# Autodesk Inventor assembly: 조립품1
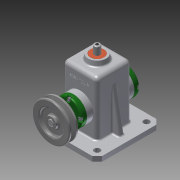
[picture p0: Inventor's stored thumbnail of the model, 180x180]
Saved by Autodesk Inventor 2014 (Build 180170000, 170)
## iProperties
Created: 2016-02
Part Number: 조립품1
Document SubType Name: Assembly
Designer: 703-05
Author: 703-05
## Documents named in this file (16)
- C:\Users\703-05\Desktop\460212V1015\답안조립품.iam
- C:\Users\703-05\Desktop\460212V1015\본체.ipt
- C:\Users\703-05\Desktop\460212V1015\V벨트풀리.ipt
- C:\Users\703-05\Desktop\460212V1015\고정핀 1.2 x 10.ipt
- C:\Users\703-05\Desktop\460212V1015\뒤커버.ipt
- C:\Users\703-05\Desktop\460212V1015\링크.ipt
- C:\Users\703-05\Desktop\460212V1015\멈춤나사 M3x8.ipt
- C:\Users\703-05\Desktop\460212V1015\베어링 12 x 32 x 10.ipt
- C:\Users\703-05\Desktop\460212V1015\볼트 M4 x 12.ipt
- C:\Users\703-05\Desktop\460212V1015\부시.ipt
- C:\Users\703-05\Desktop\460212V1015\슬라이드.ipt
- C:\Users\703-05\Desktop\460212V1015\앞커버.ipt
- C:\Users\703-05\Desktop\460212V1015\오일실 12 25 7.ipt
- C:\Users\703-05\Desktop\460212V1015\키 4 x 4 x 10.ipt
- C:\Users\703-05\Desktop\460212V1015\편심축.ipt
- C:\Users\703-05\Desktop\460212V1015\핀 5 x 18.ipt
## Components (11 placed, 4 different names)
1. V벨트풀리:1
2. 고정핀 1.2 x 10:1
3. 핀 5 x 18:1
4. ISO 4762 M4 x 12:1
5. ISO 4762 M4 x 12:2
6. ISO 4762 M4 x 12:3
7. ISO 4762 M4 x 12:4
8. ISO 4762 M4 x 12:5
9. ISO 4762 M4 x 12:6
10. ISO 4762 M4 x 12:7
11. ISO 4762 M4 x 12:8
